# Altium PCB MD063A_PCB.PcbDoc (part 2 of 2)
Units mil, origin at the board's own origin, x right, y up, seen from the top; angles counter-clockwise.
Board outline 3360 x 2682 mil, 4 copper layers (Top Layer, Signal Layer 1, Signal Layer 2, Bottom Layer), stack 61.6 mil thick; 162 components, 89 nets, 431 pads, 221 vias.
Unrouted connection lines stored in the file: 2.
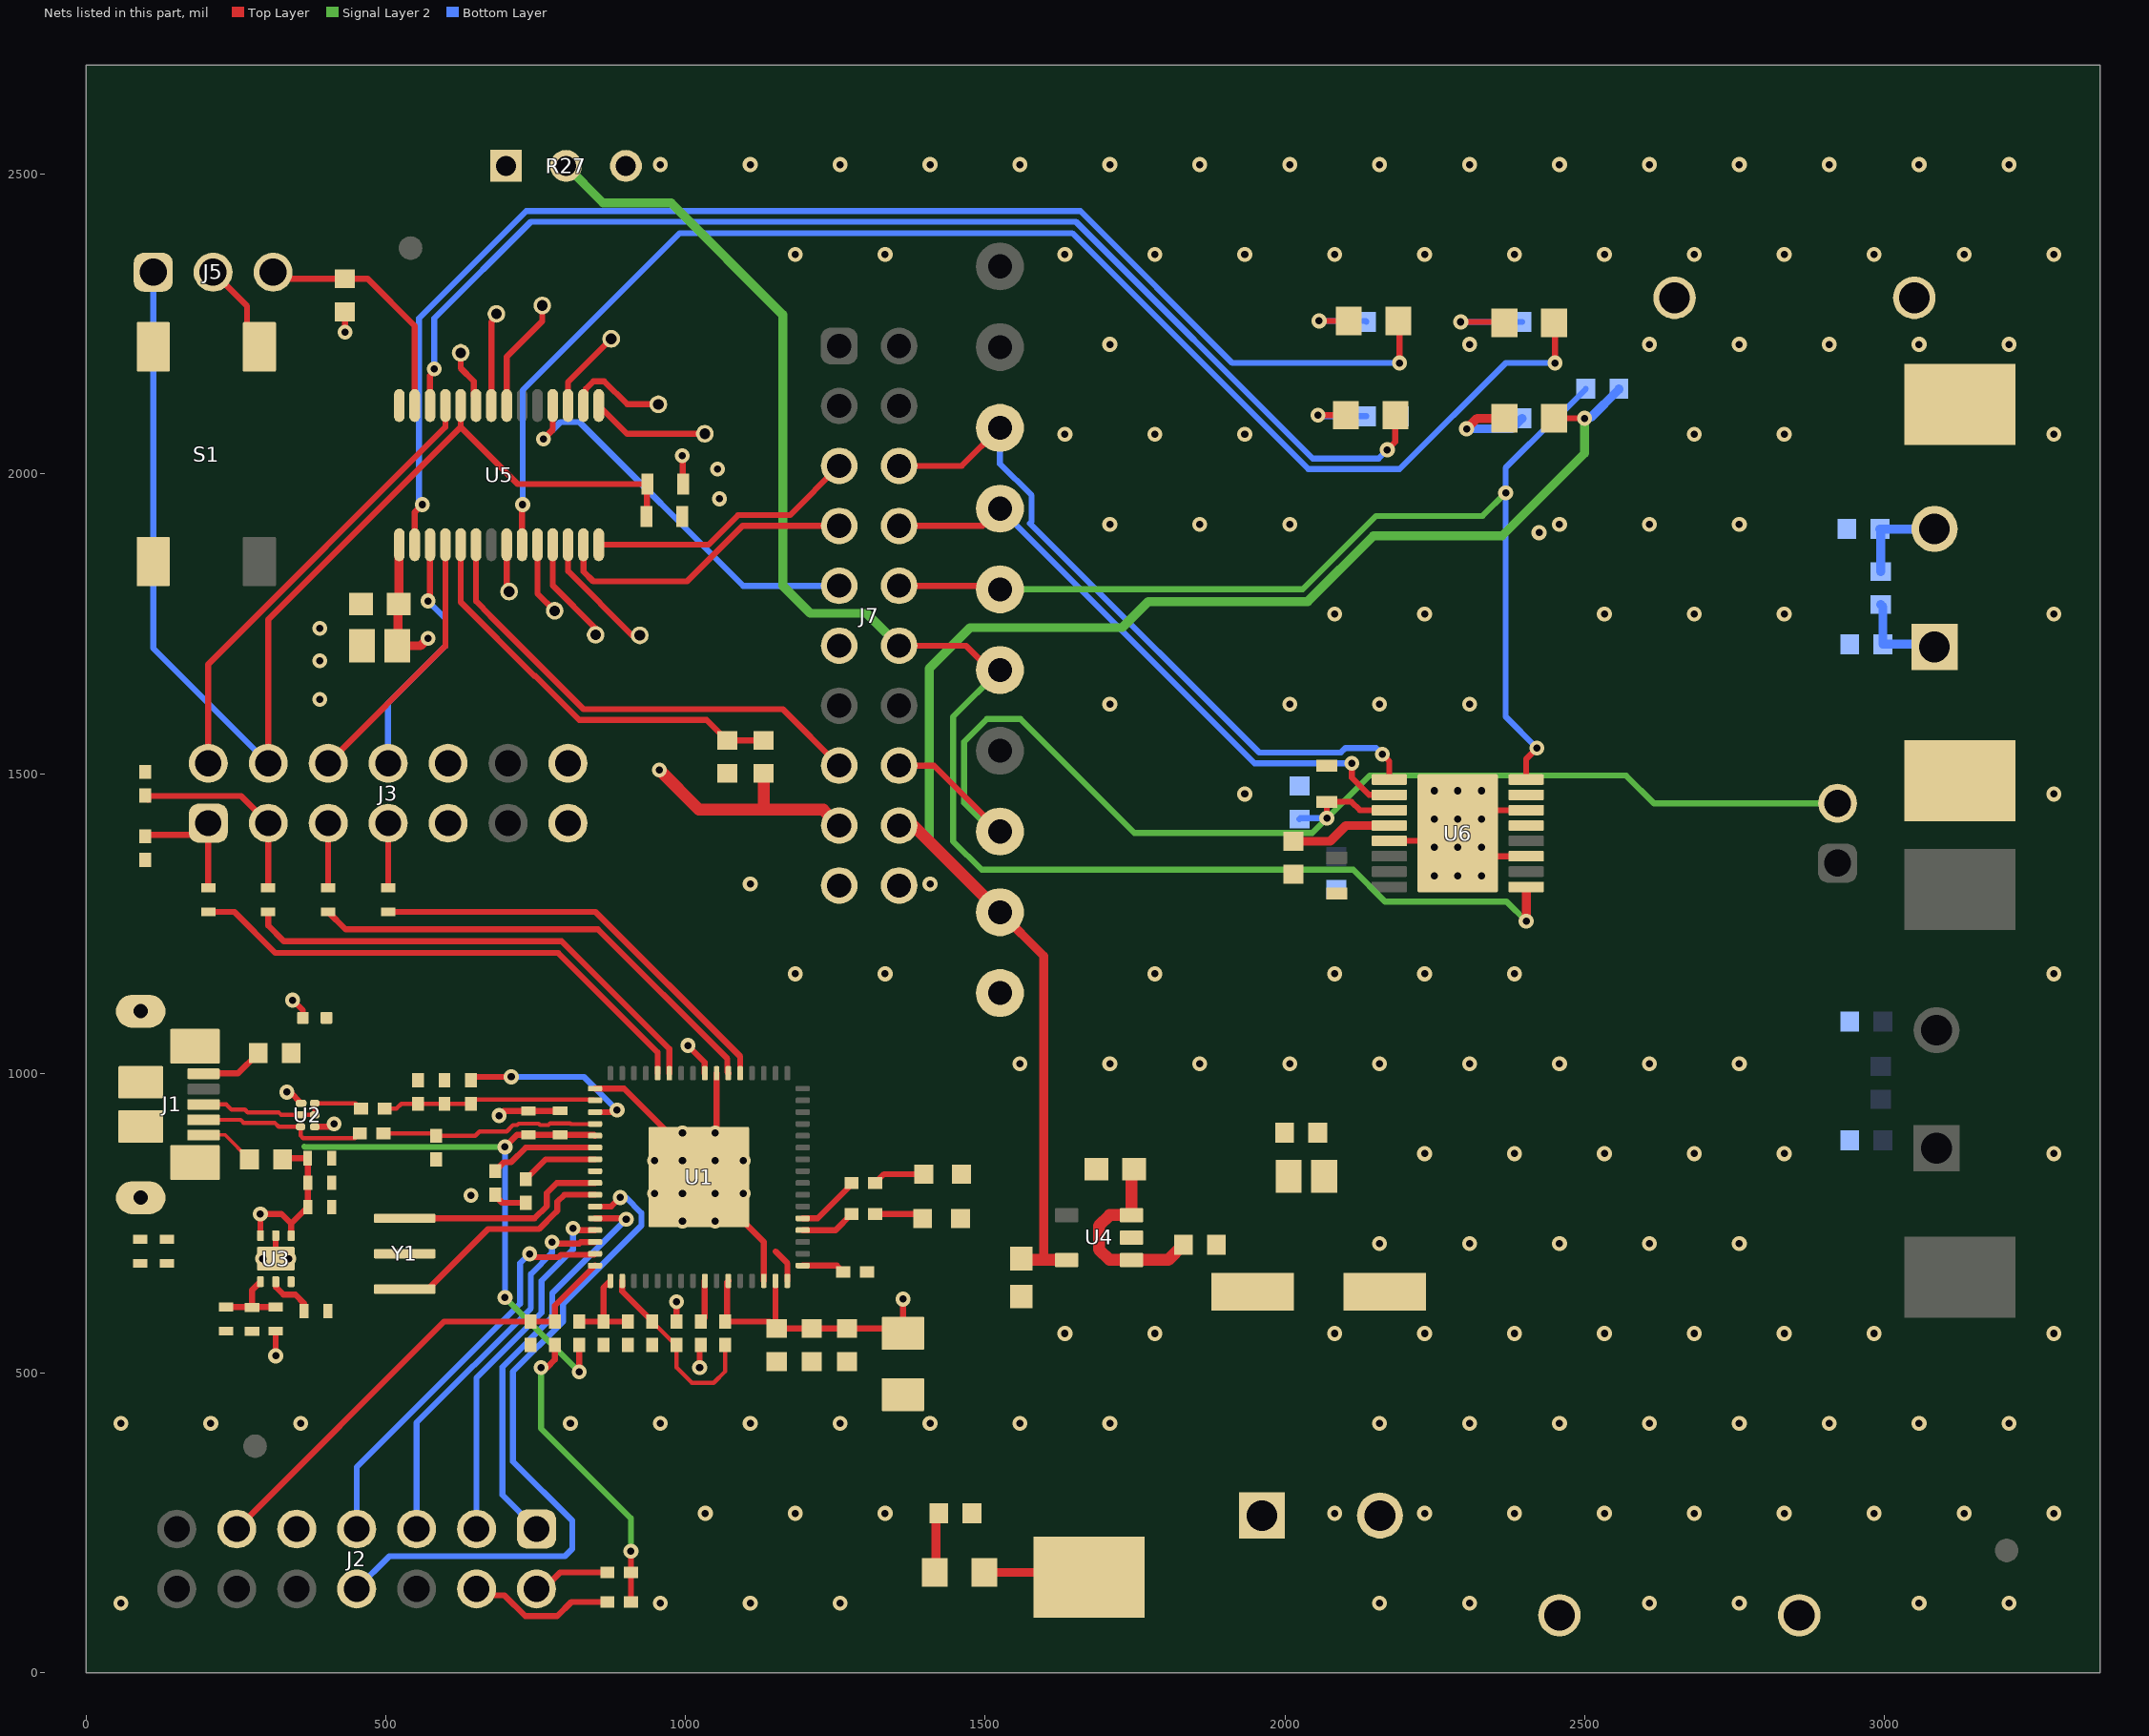
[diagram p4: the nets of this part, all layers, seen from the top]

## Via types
v1: diameter 25/25/25/25 (per signal layer), hole 12, Top Layer to Bottom Layer, 136 vias
v2: diameter 25/25/25/25 (per signal layer), hole 12, Top Layer to Bottom Layer, tented both sides, 85 vias

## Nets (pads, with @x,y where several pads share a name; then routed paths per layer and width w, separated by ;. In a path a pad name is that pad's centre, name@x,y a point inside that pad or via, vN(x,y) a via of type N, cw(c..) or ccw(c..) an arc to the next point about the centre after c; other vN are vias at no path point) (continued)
BIN1: J7.6 TP18.1 U6.9 | length 1177.7
  Top Layer w10: J7.6@1356.4,2013.34 1461.11,2013.34 TP18.1@1524.61,2076.84 ; v2(2162.56,1532.28) 2174.17,1520.67 U6.9@2174.17,1490.11
  Bottom Layer w10: TP18.1@1524.61,2076.84 1524.61,2016.92 1577.48,1964.05 1577.48,1920.25 1574.63,1917.4 1619.16,1872.88 1956.84,1535.2 2093.41,1535.2 2100.91,1542.7 2152.14,1542.7 v2(2162.56,1532.28)
BIN1_MCU: J7.5 U5.14 | length 455.5
  Top Layer w10: U5.14@855.32,1881.89 1038.52,1881.89 1087.85,1931.22 1174.27,1931.22 J7.5@1256.4,2013.34
BIN2: J7.8 TP19.1 U6.10 | length 1041.5
  Top Layer w10: J7.8@1356.4,1913.34 1495.8,1913.34 TP19.1@1524.61,1942.15 ; v2(2111.42,1517.32) 2111.42,1493.45 2140.34,1464.52 U6.10@2174.17,1464.52
  Bottom Layer w10: TP19.1@1524.61,1942.15 1949.43,1517.32 v2(2111.42,1517.32)
BIN2_MCU: J7.7 U5.13 | length 516.6
  Top Layer w10: U5.13@829.72,1881.89 829.72,1837.21 846.23,1820.71 1002.61,1820.71 1095.25,1913.34 J7.7@1256.4,1913.34
BIPROPI: C36.1 J6.2 J7.16 R25.2 TP23.1 U6.11 | length 2189.8
  Top Layer w10: J7.16@1356.4,1513.34 1414.65,1513.34 TP23.1@1524.61,1403.39 ; v2(2070,1425.48) R25.2@2070,1453.03 2110.95,1453.03 2125.05,1438.93 U6.11@2174.17,1438.93
  Signal Layer 2 w10: TP23.1@1524.61,1403.39 1512.36,1403.39 1464.57,1451.19 1464.57,1552.82 1502.71,1590.95 1558.97,1590.95 1748.84,1401.08 2045.6,1401.08 v2(2070,1425.48) 2141.31,1496.79 2569.36,1496.79 2615.6,1450.55 J6.2@2922,1450.55
  Bottom Layer w10: C36.1@2024.2,1424.17 2025.51,1425.48 v2(2070,1425.48)
BIPROPI_MCU: J7.15 U5.6 | length 814.1
  Top Layer w10: U5.6@650.59,1881.89 650.59,1787.53 674.9,1763.23 674.9,1762.61 830.03,1607.48 1162.26,1607.48 J7.15@1256.4,1513.34
BOUT1: C39.2 C40.1 J9.2 TP15.1 U6.7 | length 218.6
  Top Layer w15: TP15.1@3126,2060.12 TP15.1@3126,2116.14
  Bottom Layer w15: C39.2@2994,1837.12 2994,1906.68 C40.1@2992.68,1908 3083.49,1908 J9.2@3083.72,1908.23
BOUT2: C39.1 C42.1 J9.1 TP14.1 U6.5 | length 211.6
  Top Layer w15: TP14.1@3126,1488 TP14.1@3126,1544.03
  Bottom Layer w15: C39.1@2994,1782 2997.56,1778.44 C42.1@2997.56,1716 3079.1,1716 J9.1@3083.72,1711.38
DEV_ID: R21.1 R22.2 U5.5 | length 697.1
  Top Layer w10: U5.5@625,1881.89 625,1785.81 748.21,1662.6 749.63,1662.6 822.62,1589.61 1035.29,1589.61 R22.2@1069.44,1555.46 R21.1@1130.58,1555.46
EZFET_AVBUS: C18.1 R14.1 R15.2 U1.1 | length 153.6
  Top Layer w10: R14.1@822.83,586.01 C18.1@863.43,586.01 ; U1.1@874.68,653.73 863.43,642.48 C18.1@863.43,586.01 ; R15.2@904.03,586.01 C18.1@863.43,586.01
EZFET_AVCC2ADC: C19.1 R16.1 R17.2 U1.2 | length 326.4
  Top Layer w7: C19.1@944.63,586.01 984,546.64 R17.2@985.23,546.64 985.23,509.11 1010.7,483.65 1047.1,483.65 1066.44,502.98 R16.1@1066.44,546.64
  Top Layer w10: U1.2@894.36,653.73 894.36,636.28 C19.1@944.63,586.01
EZFET_D_N: C11.1 R4.2 U1.52 | length 365.8
  Top Layer w7: R4.2@496.06,900 580.01,900 C11.1@584.15,895.85 649.3,895.85 656.58,903.14 701.65,903.14 712.14,913.63 718.98,913.63 721.48,916.13 754.9,916.13 757.4,913.63 771.38,913.63 774.13,916.38 807.56,916.38 808.58,915.35 848.9,915.35 U1.52@849.09,915.54
EZFET_D_P: C12.1 R5.2 R6.2 R7.1 U1.50 | length 358.9
  Top Layer w7: R5.2@498.02,940.95 517.72,940.95 525.77,949 R6.2@553.64,949 C12.1@597.93,949 R7.1@642.22,949 648.13,954.91 648.13,956.38 847.61,956.38 U1.50@849.09,954.91
EZFET_LED0: R1.2 U1.20 | length 92.6
  Top Layer w10: U1.20@1195.54,738.37 1250.29,738.37 R1.2@1277.07,765.14
EZFET_LED1: R2.2 U1.21 | length 107.2
  Top Layer w10: U1.21@1195.54,758.06 1220.47,758.06 1277.07,814.65 R2.2@1277.07,816.93
EZFET_PUR: R7.2 U1.51 | length 307.1
  Top Layer w10: R7.2@642.22,988.37 647.95,994.09 v2(709.33,994.09) ; U1.51@849.09,935.22 882.14,935.22 v2(885.83,938.91)
  Bottom Layer w10: v2(709.33,994.09) 830.64,994.09 v2(885.83,938.91)
EZFET_RST: C24.1 J2.11 R19.1 U1.64 | length 795.3
  Top Layer w10: J2.11@251.38,239.76 597.62,586.01 C24.1@741.63,586.01 R19.1@782.23,586.01 782.23,612.46 U1.64@849.09,679.32
EZFET_TCK: J2.7 U1.63 | length 692.6
  Top Layer w10: v2(739.87,698.82) 745.56,693.13 788.07,693.13 792.13,697.19 847.27,697.19 U1.63@849.09,699
  Bottom Layer w10: J2.7@451.38,239.76 451.38,342.66 724.19,615.47 724.19,683.14 v2(739.87,698.82)
EZFET_TDI: J2.3 U1.61 | length 606.4
  Top Layer w10: v2(812.36,741.49) 815.48,738.37 U1.61@849.09,738.37
  Bottom Layer w10: J2.3@651.38,239.76 651.38,492.1 759.94,600.67 759.94,653.73 812.36,706.14 v2(812.36,741.49)
EZFET_TDO: J2.1 U1.60 | length 678.5
  Top Layer w10: U1.60@849.09,758.06 899.35,758.06 v2(901.08,756.33)
  Bottom Layer w10: J2.1@751.38,239.76 694.39,296.75 694.39,509.84 777.81,593.26 777.81,633.06 v2(901.08,756.33)
EZFET_TEST: J2.8 U1.59 | length 1171.8
  Top Layer w10: U1.59@849.09,777.74 876.17,777.74 v2(891.29,792.86)
  Bottom Layer w10: J2.8@451.38,139.76 506.02,194.41 799,194.41 811.15,206.56 811.15,253.64 712.26,352.53 712.26,502.43 795.69,585.86 795.69,615.05 926.46,745.82 926.46,766.84 900.43,792.86 v2(891.29,792.86)
EZFET_TMS: J2.5 U1.62 | length 646
  Top Layer w10: v2(777.56,718.5) 779.94,716.12 822.87,716.12 825.25,718.5 848.9,718.5 U1.62@849.09,718.69
  Bottom Layer w10: J2.5@551.38,239.76 551.38,417.38 742.07,608.07 742.07,665.13 777.56,700.62 v2(777.56,718.5)
EZFET_UARTRXD: R10.1 U1.38 | length 792.3
  Top Layer w10: R10.1@403.86,1269.37 433.08,1240.16 854,1240.16 1069.72,1024.44 1069.72,1001.99 U1.38@1071.53,1000.18
EZFET_UARTTXD: R11.1 U1.37 | length 715.1
  Top Layer w10: R11.1@504.05,1269.37 850.06,1269.37 1091.21,1028.22 U1.37@1091.21,1000.18
EZFET_USB_Shield: C5.1 J1.6 J1.7 J1.8 J1.9 J1.10 J1.11 R3.2
EZFET_V18: C2.1 U1.55 | length 129
  Top Layer w10: C2.1@733.76,823.36 766.88,856.48 U1.55@849.09,856.48
EZFET_VBUS: C9.2 C13.1 C14.1 C15.1 C23.1 C25.1 L1.2 R14.2 U1.53 U2.1 U3.4 U3.6 | length 1311.4
  Top Layer w10: U3.6@290.85,729.15 290.85,764.99 v2(290.69,765.14) 325.96,765.14 342.03,749.08 ; L1.2@327.87,856.48 329.79,858.4 C13.1@369.59,858.4 369.9,858.09 C14.1@369.9,817.46 C15.1@369.9,776.96 342.03,749.08 ; v2(334.76,968.69) 340.25,968.69 U2.1@358.76,950.18 ; U3.4@342.03,729.15 342.03,749.08 ; v2(344.49,1122.05) 361.71,1104.82 C9.2@361.71,1092.52 ; v2(698.82,877.15) 718.92,897.26 C25.1@738.19,897.26 790.6,897.26 C23.1@790.85,897.51 847.43,897.51 U1.53@849.09,895.85 ; v2(822.83,501.97) R14.2@822.83,546.64
  Signal Layer 2 w10: 364.17,877.97 364.99,877.15 v2(698.82,877.15) ; v2(698.82,625.98) v2(822.83,501.97)
  Bottom Layer w10: v2(698.82,625.98) v2(698.82,877.15)
EZFET_VCC: C6.1 C7.1 C8.1 C10.1 J3.9 R12.1 R13.1 R16.2 R18.2 R19.2 U1.11 U1.15 U1.40 | length 1114.6
  Top Layer w10: v2(316.44,528.71) R18.2@316.44,569.95 ; v2(758.86,509.11) 769.02,509.11 782.23,522.33 R19.2@782.23,546.64 ; R12.1@908.96,118.11 R13.1@908.96,167.32 v2(908.96,202.69) ; v2(1003.94,1046.44) 1032.16,1018.22 U1.40@1032.16,1000.18 ; U1.11@1071.53,653.73 1069.44,651.64 1069.44,589.01 R16.2@1066.44,586.01 1140.29,586.01 C7.1@1150.27,576.04 ; U1.15@1150.27,653.73 C7.1@1150.27,576.04 ; v2(1362.73,623.41) C6.1@1362.73,566.33 1354.86,574.2 C10.1@1269.19,574.2 C8.1@1210.65,574.2 C7.1@1152.1,574.2 C7.1@1150.27,576.04
  Signal Layer 2 w10: v2(758.86,509.11) 758.86,407.55 908.96,257.46 v2(908.96,202.69)
EZFET_VCORE: C3.1 U1.17 | length 72.1
  Top Layer w10: U1.17@1195.54,679.32 1252.66,679.32 C3.1@1263.29,668.69
EZFET_VREF: C1.1 U1.9 | length 70.3
  Top Layer w10: C1.1@1025.83,586.01 1032.16,592.33 U1.9@1032.16,653.73
EZFET_VUSB: C4.1 U1.54 | length 182.7
  Top Layer w10: C4.1@682.58,836.99 697.36,851.78 709.33,851.78 733.72,876.17 U1.54@849.09,876.17
EZFET_XT2IN: U1.57 Y1.1 | length 355
  Top Layer w10: Y1.1@531.5,758.06 748.21,758.06 768.45,778.3 768.45,800.38 785.19,817.11 U1.57@849.09,817.11
EZFET_XT2OUT: U1.58 Y1.3 | length 389.5
  Top Layer w10: Y1.3@531.5,639.95 570.53,639.95 670.77,740.18 755.62,740.18 783.68,768.25 ; 785.19,769.75 786.33,770.89 786.33,785.97 797.78,797.43 U1.58@849.09,797.43
GND: C1.2 C2.2 C3.2 C4.2 C5.2 C6.2 C7.2 C8.2 C9.1 C10.2 C11.2 C12.2 C13.2 C14.2 C15.2 C16.1 C17.1 C18.2 C19.2 C20.2 C21.2 C22.2 C23.2 C24.2 C25.2 C26.2 C27.2 C28.2 C29.2 C30.2 C31.2 C32.2 C33.2 C34.2 C35.2 C36.2 C38.2 C40.2 C41.2 C42.2 D1.1 D2.1 J2.9 J3.13 J3.14 J4.2 J7.19 J7.20 L2.2 R3.1 R6.1 R15.1 R17.1 R22.1 R24.1 R25.1 R27.3 R28.1 R29.1 R30.1 R31.1 S1.3 S1.4 TP6.1 TP6.2 TP7.1 TP7.2 TP25.1 U1.14 U1.16 U1.39 U1.49 U1.56 U1.65 U2.4 U3.3 U3.5 U3.7@316.44,690.76 U4.2 U5.28 U6.3 U6.6 U6.13 U6.17 Y1.2 | length 1385.4
  Top Layer w10: U3.7@316.44,690.76 U3.5@316.44,729.15 ; U2.4@381.4,910.81 409.01,910.81 v2(413.73,915.54) ; C4.2@682.58,797.62 682.58,795.66 694.24,783.99 C2.2@733.76,783.99 ; v2(688.98,929.51) 696.72,937.26 C25.2@738.19,937.26 790.6,937.26 C23.2@790.85,937.51 ; U1.49@849.09,974.59 897.4,974.59 1022.31,849.68 U1.65@1022.31,826.96 ; R17.1@985.23,586.01 v2(985.23,618.8) ; v2(1023.62,509.11) 1023.62,544.43 C1.2@1025.83,546.64 ; U1.39@1051.84,1000.18 1051.84,856.48 v2(1049.68,854.32) U1.65@1022.31,826.96 ; U1.14@1130.58,653.73 1130.58,718.69 v2(1049.68,799.59) U1.65@1022.31,826.96 ; 1150.27,702.78 1169.95,683.1 U1.16@1169.95,653.73 ; U6.13@2174.17,1387.75 2275.55,1387.75 U6.17@2288.34,1400.55 ; U6.17@2319.84,1369.05 U6.17@2288.34,1400.55 ; U6.17@2326.73,1362.16 U6.3@2402.51,1362.16 ; U6.6@2402.51,1438.93 2326.73,1438.93 U6.17@2288.34,1400.55
  other v1: 58,116 958,116 1108,116 1258,116 2158,116 2308,116 2608,116 2758,116 3058,116 3208,116 1033,266 1183,266 1333,266 2083,266 2233,266 2383,266 2533,266 2683,266 2833,266 2983,266 3133,266 3283,266 58,416 208,416 358,416 808,416 958,416 1108,416 1258,416 1408,416 1558,416 1708,416 2158,416 2308,416 2458,416 2608,416 2758,416 2908,416 3058,416 3208,416 1633,566 1783,566 2083,566 2233,566 2383,566 2533,566 2683,566 2833,566 2983,566 3283,566 2158,716 2308,716 2458,716 2608,716 2758,716 2233,866 2383,866 2533,866 2683,866 2833,866 3283,866 1558,1016 1708,1016 1858,1016 2008,1016 2158,1016 2308,1016 2458,1016 2608,1016 2758,1016 1183,1166 1333,1166 1783,1166 2083,1166 2233,1166 2383,1166 3283,1166 1108,1316 1408,1316 1933,1466 3283,1466 1708,1616 2008,1616 2158,1616 2308,1616 2083,1766 2233,1766 2533,1766 2683,1766 2833,1766 3283,1766 1708,1916 1858,1916 2008,1916 2458,1916 2608,1916 2758,1916 1633,2066 1783,2066 1933,2066 2683,2066 2833,2066 3283,2066 1708,2216 2608,2216 2758,2216 2908,2216 3058,2216 3208,2216 1183,2366 1333,2366 1633,2366 1783,2366 1933,2366 2083,2366 2233,2366 2383,2366 2533,2366 2683,2366 2833,2366 2983,2366 3133,2366 3283,2366 958,2516 1108,2516 1258,2516 1408,2516 1558,2516 1708,2516 1858,2516 2008,2516 2158,2516 2308,2516 2608,2516 3058,2516 3208,2516
  other v2: 294.78,690.76 338.09,690.76 994.95,753.14 1049.68,753.14 642.22,796.41 948.49,799.59 994.95,799.59 1096.13,799.59 948.49,854.32 994.95,854.32 1096.13,854.32 994.95,900.77 1049.68,900.77 2248.97,1329.68 2288.34,1329.68 2327.71,1329.68 2248.97,1376.93 2288.34,1376.93 2327.71,1376.93 2248.97,1424.17 2288.34,1424.17 2327.71,1424.17 2248.97,1471.41 2288.34,1471.41 2327.71,1471.41 389.71,1624.02 389.71,1688.45 389.71,1742.46 2424,1902 1056.54,1958.44 1053.38,2007.87 2308,2216 2458,2516 2758,2516 2908,2516
GUI_STATUS: D4.2 U5.9 | length 2393.4
  Top Layer w10: U5.9@727.36,1881.89 727.36,1947.83 v2(728.35,1948.82) ; D4.2@2448.82,2252.02 2450.79,2250.05 v2(2450.79,2185.04)
  Bottom Layer w10: v2(728.35,1948.82) 728.35,2139.61 990.43,2401.69 1645.1,2401.69 2038.92,2007.87 2191.1,2007.87 2368.26,2185.04 v2(2450.79,2185.04)
MCU_STATUS: D3.2 U5.2 | length 2271.2
  Top Layer w10: U5.2@548.23,1881.89 548.23,1936.02 v2(561.02,1948.82) ; D3.2@2189.13,2255.17 2191.1,2253.2 v2(2191.1,2185.04)
  Bottom Layer w10: v2(561.02,1948.82) 555.33,1954.51 555.33,2259.64 734.22,2438.52 1658.82,2438.52 1912.31,2185.04 v2(2191.1,2185.04)
MCU_UARTRXD: J3.8 U5.3 | length 417.6
  Top Layer w10: v2(570.37,1787.95) 573.82,1791.39 U5.3@573.82,1881.89
  Bottom Layer w10: J3.8@503.86,1517.32 503.86,1617.32 599.41,1712.87 599.41,1758.91 v2(570.37,1787.95)
MCU_UARTTXD: J3.6 U5.4 | length 445.6
  Top Layer w10: J3.6@403.86,1517.32 599.41,1712.87 U5.4@599.41,1881.89
NetC16_2: C16.2 J3.1 R8.2 | length 216.6
  Top Layer w10: C16.2@103.34,1397.64 184.18,1397.64 J3.1@203.86,1417.32 R8.2@203.86,1309.37
NetC17_2: C17.2 J3.3 R9.2 | length 333.2
  Top Layer w10: C17.2@103.34,1456.69 103.34,1462.68 258.51,1462.68 J3.3@303.86,1417.32 R9.2@303.86,1309.37
NetC20_1: C20.1 U3.2 | length 80.2
  Top Layer w10: U3.2@316.44,652.38 316.44,643.36 329.16,630.64 349.11,630.64 363.68,616.08 C20.1@363.68,603.41
NetC21_1: C21.1 C22.1 R18.1 U3.1 | length 131.2
  Top Layer w10: C22.1@233.76,609.95 C21.1@276.91,609.95 ; C21.1@276.91,609.63 C21.1@276.91,609.95 ; U3.1@290.85,652.38 276.91,638.44 C21.1@276.91,609.95 ; R18.1@316.44,609.95 C21.1@276.91,609.95
NetC26_1: C26.1 R20.1 U4.1 U4.3 | length 337.8
  Top Layer w15: C26.1@1743.98,837.35 C26.1@1746.98,840.36
  Top Layer w20: C26.1@1743.98,837.35 U4.3@1743.98,763.4 1707.56,763.4 1689.84,745.68 1689.84,706.31 1707.56,688.6 U4.1@1743.98,688.6 1805.31,688.6 R20.1@1830.71,714
NetD1_2: D1.2 R1.1 | length 82.2
  Top Layer w10: R1.1@1316.44,765.14 1388.4,765.14 D1.2@1395.67,757.87
NetD2_2: D2.2 R2.1 | length 87.4
  Top Layer w10: R2.1@1316.44,816.93 1331.38,831.88 D2.2@1397.64,831.88
NetD3_1: D3.1 R28.2 | length 128.9
  Top Layer w10: v2(2057.09,2255.17) D3.1@2106.45,2255.17
  Bottom Layer w10: v2(2057.09,2255.17) 2134.55,2255.17 R28.2@2135.98,2253.74
NetD4_1: D4.1 R29.2 | length 175.8
  Top Layer w10: v2(2293.31,2253.54) 2364.61,2253.54 D4.1@2366.14,2252.02
  Bottom Layer w10: v2(2293.31,2253.54) R29.2@2395.67,2253.54
NetD5_1: D5.1 R30.2 | length 128
  Top Layer w10: v2(2055.07,2097.79) D5.1@2101.53,2097.79
  Bottom Layer w10: v2(2055.07,2097.79) 2056.5,2096.37 R30.2@2135.98,2096.37
NetD6_1: D6.1 R31.2 | length 92.6
  Top Layer w15: D6.1@1417.81,175.38 1417.81,261.01 R31.2@1422.73,265.93
NetD7_1: D7.1 R33.2 | length 169.9
  Top Layer w15: v2(2303.15,2075.26) 2320.56,2092.67 D7.1@2366.14,2092.67
  Bottom Layer w15: v2(2303.15,2075.26) 2378.26,2075.26 R33.2@2395.67,2092.67
NetJ1_1: J1.1 L1.1 | length 94.2
  Top Layer w6: J1.1@195.86,896.9 196.5,897.54 231.69,897.54 L1.1@272.75,856.48
NetJ1_5: J1.5 L2.1 | length 105.5
  Top Layer w10: J1.5@195.86,999.26 196.5,999.9 253.36,999.9 L2.1@287.11,1033.65
NetJ2_2: J2.2 R13.2 | length 129.6
  Top Layer w10: J2.2@751.38,139.76 763.4,139.76 790.96,167.32 R13.2@869.59,167.32
NetJ2_4: J2.4 R12.2 | length 246.8
  Top Layer w10: J2.4@651.38,139.76 661.89,129.25 697.75,129.25 732.59,94.41 785.83,94.41 809.53,118.11 R12.2@869.59,118.11
NetJ3_5: J3.5 R10.2 | length 108
  Top Layer w10: R10.2@403.86,1309.37 J3.5@403.86,1417.32
NetJ3_7: J3.7 R11.2 | length 108
  Top Layer w10: J3.7@503.86,1417.32 504.05,1417.14 R11.2@504.05,1309.37
NetJ5_2: J5.2 S1.1 | length 156.4
  Top Layer w10: J5.2@212,2336.43 268.54,2279.89 268.54,2232.64 S1.1@289.17,2212.01
NetTP2_1: TP2.1 U5.23 | length 98.4
  Top Layer w10: TP2.1@625,2201.94 625,2176.34 646.73,2154.61 646.73,2129.6 650.59,2125.74 U5.23@650.59,2114.17
NetTP3_1: TP3.1 U5.8 | length 79.8
  Top Layer w10: U5.8@701.77,1881.89 701.77,1807.63 TP3.1@705.71,1803.7
NetTP4_1: TP4.1 U5.15 | length 196.4
  Top Layer w10: U5.15@855.32,2114.17 902.56,2066.93 TP4.1@1032.16,2066.93
NetTP5_1: TP5.1 U5.21 | length 191.3
  Top Layer w10: U5.21@701.77,2114.17 701.77,2195.51 761.1,2254.84 TP5.1@761.1,2280.91
NetTP8_1: TP8.1 U5.16 | length 172.8
  Top Layer w10: U5.16@829.72,2114.17 831.69,2116.14 833.58,2116.14 833.58,2141.88 846.31,2154.61 864.32,2154.61 902.78,2116.14 TP8.1@954.72,2116.14
NetTP9_1: TP9.1 U5.12 | length 208.2
  Top Layer w10: U5.12@804.13,1881.89 804.13,1837.52 911.02,1730.64 TP9.1@923.65,1730.64
NetTP10_1: TP10.1 U5.11 | length 180
  Top Layer w10: U5.11@778.54,1881.89 778.54,1813.98 850.06,1742.46 TP10.1@850.06,1731.55
NetTP11_1: TP11.1 U5.10 | length 122.2
  Top Layer w10: U5.10@752.95,1881.89 752.95,1800.48 TP11.1@781.78,1771.65
NetTP26_1: TP26.1 U5.22 | length 156.3
  Top Layer w10: U5.22@676.18,2114.17 676.18,2253.42 684.48,2261.72 TP26.1@684.48,2267
NetTP27_1: TP27.1 U5.17 | length 141
  Top Layer w10: U5.17@804.13,2114.17 804.13,2153.46 TP27.1@876.06,2225.38
nFAULT: J7.10 R32.1 R33.1 TP20.1 U6.8 | length 1818.4
  Top Layer w10: J7.10@1356.4,1813.34 1518.72,1813.34 TP20.1@1524.61,1807.46 ; U6.8@2402.51,1490.11 2402.51,1524.78 v2(2420.43,1542.7)
  Signal Layer 2 w10: TP20.1@1524.61,1807.46 2029.73,1807.46 2152.14,1929.87 2329.63,1929.87 v2(2368.26,1968.5)
  Bottom Layer w10: v2(2420.43,1542.7) 2368.26,1594.86 2368.26,2010.15 R33.1@2450.79,2092.67 2452.67,2092.67 R32.1@2502,2142
nFAULT_MCU: J7.9 U5.18 | length 681
  Top Layer w10: v2(762.87,2058.04) 778.54,2073.72 U5.18@778.54,2114.17
  Bottom Layer w10: v2(762.87,2058.04) 791.24,2086.42 823.03,2086.42 1096.11,1813.34 J7.9@1256.4,1813.34
PUSH: J5.3 R26.1 U5.27 | length 406.1
  Top Layer w10: J5.3@312,2336.43 322.96,2325.47 R26.1@432,2325.47 469.79,2325.47 548.23,2247.03 U5.27@548.23,2114.17
RST/SBWTDIO: C35.1 J3.4 J5.1 R23.1 U5.24 | length 2033.9
  Top Layer w10: J3.4@303.86,1517.32 303.86,1757.01 625,2078.14 ; U5.24@625,2114.17 625,2078.14 ; C35.1@934.67,1929.21 935.56,1930.1 935.56,1982.14 R23.1@936.45,1983.03 720.11,1983.03 625,2078.14
  Bottom Layer w10: J5.1@112,2336.43 112,1709.19 J3.4@303.86,1517.32
STALL: D5.2 U5.26 | length 2037.7
  Top Layer w10: U5.26@573.82,2114.17 573.82,2164.25 580.71,2171.14 v2(580.71,2175.2) ; v2(2170.87,2040.16) 2184.21,2053.5 D5.2@2184.21,2097.79
  Bottom Layer w10: v2(580.71,2175.2) 580.71,2259.39 741.97,2420.65 1651.42,2420.65 2046.32,2025.75 2156.46,2025.75 v2(2170.87,2040.16)
T_RST_RST: R9.1 U1.43 | length 818
  Top Layer w10: R9.1@303.86,1269.37 303.86,1246.4 329.79,1220.47 793.47,1220.47 973.1,1040.85 U1.43@973.1,1000.18
T_TEST_TCKC: R8.1 U1.44 | length 881.6
  Top Layer w10: R8.1@203.86,1269.37 247.48,1269.37 316.06,1200.79 787.88,1200.79 953.42,1035.25 U1.44@953.42,1000.18
TST/SBWTCK: J3.2 U5.25 | length 760.7
  Top Layer w10: J3.2@203.86,1517.32 203.86,1682.28 599.41,2077.83 U5.25@599.41,2114.17
USB_D_N: J1.2 R4.1 U2.3 | length 285.7
  Top Layer w7: J1.2@195.86,922.49 257.84,922.49 262.82,917.51 314.66,917.51 321.36,910.81 U2.3@357.77,910.81 357.77,896.17 362.03,891.92 362.14,892.03 384,892.03 384.37,891.66 423.62,891.66 423.99,892.03 448.73,892.03 R4.1@456.69,900
USB_D_P: J1.3 R5.1 U2.2 U2.5 U2.6 | length 293.6
  Top Layer w7: J1.3@195.86,948.08 233.79,948.08 235.9,945.97 242.38,939.49 264.88,939.49 269.87,934.51 321.71,934.51 325.71,930.5 U2.2@357.77,930.5 U2.5@381.4,930.5 U2.6@381.4,950.18 449.42,950.18 R5.1@458.65,940.95
VCC: C27.1 C29.1 C32.1 D7.2 J3.10 J7.17 J7.18 R21.2 R23.2 R26.2 R27.1 R32.2 TP24.1 U4.5 U5.1 | length 3507
  Top Layer w10: v2(432,2236.29) R26.2@432,2270.35 ; v2(994.67,2030.31) 995.56,2029.42 995.56,1983.92 R23.2@996.45,1983.03 ; D7.2@2448.82,2092.67 v2(2500,2092.67)
  Top Layer w15: U5.1@522.64,1881.89 522.15,1881.4 522.15,1783.52 C29.1@521.65,1783.03 520.42,1781.8 520.42,1714.57 C27.1@519.19,1713.34 558.07,1713.34 v2(570.37,1725.64) ; TP24.1@1524.61,1268.7 1597.51,1195.79 1597.51,689.25
  Top Layer w20: v2(956.45,1506.01) 1022.74,1439.72 1131.89,1439.72 ; R21.2@1130.58,1500.34 1130.58,1441.03 1131.89,1439.72 ; J7.17@1256.4,1413.34 1230.02,1439.72 1131.89,1439.72 ; J7.18@1356.4,1413.34 1379.97,1413.34 TP24.1@1524.61,1268.7 ; C32.1@1559.97,689.25 1597.51,689.25 1635.05,689.25 U4.5@1635.71,688.6
  Signal Layer 2 w15: TP24.1@1524.61,1268.7 1406.4,1386.91 1406.4,1675.24 1474.67,1743.52 1728.52,1743.52 1772.09,1787.09 2038.17,1787.09 2147.72,1896.63 2362.2,1896.63 2500,2034.43 v2(2500,2092.67)
  Bottom Layer w15: v2(2500,2092.67) 2501.91,2094.59 2510.69,2094.59 2557.12,2141.02 R32.2@2557.12,2142
VM: C28.1 C30.1 C31.1 C33.1 D6.2 J4.1 R20.2 TP1.1 U6.12 | length 348.7
  Top Layer w15: D6.2@1498.49,167.32 1665.1,167.32 TP1.1@1673.23,159.19 ; C33.1@2014.46,1387.12 2075.48,1387.12 2101.71,1413.34 U6.12@2174.17,1413.34
VREF: J7.12 R27.2 TP21.1 U6.1 | length 2723.8
  Top Layer w10: J7.12@1356.4,1713.34 1467.87,1713.34 1508.44,1672.77 TP21.1@1524.61,1672.77
  Top Layer w15: v2(2402.51,1253.71) U6.1@2402.51,1310.98
  Signal Layer 2 w10: TP21.1@1524.61,1672.77 1446.69,1594.86 1446.69,1386.93 1494.09,1339.52 2113.84,1339.52 2166.93,1286.43 2369.79,1286.43 v2(2402.51,1253.71)
  Signal Layer 2 w15: R27.2@800.61,2514 862.62,2451.99 975.95,2451.99 1162.26,2265.69 1162.26,1813.34 1208.14,1767.46 1302.28,1767.46 J7.12@1356.4,1713.34
VREF_MCU: J7.11
pads on no net: FID1.1 FID2.1 FID3.1 H1.0 H2.0 H3.0 H4.0 J1.4 J2.6 J2.10 J2.12 J2.13 J2.14 J3.11 J3.12 LBL1.0 S1.2 SH-J1.0 SH-J2.0 SH-J3.0 SH-J4.0 SH-J5.0 SH-J6.0 SH-J7.0 SH-J10.0 SH-J11.0 SH-J12.0 SH-J13.0 SH-J14.0 SH-J15.0 SH-J16.0 SH-J17.0 SH-J18.0 SH-J19.0 SH-J20.0 U1.3 U1.4 U1.5 U1.6 U1.7 U1.8 U1.10 U1.12 U1.13 U1.18 U1.19 U1.22 U1.23 U1.24 U1.25 U1.26 U1.27 U1.28 U1.29 U1.30 U1.31 U1.32 U1.33 U1.34 U1.35 U1.36 U1.41 U1.42 U1.45 U1.46 U1.47 U1.48 U3.7@298.72,690.76 U3.7@334.15,690.76 U4.4

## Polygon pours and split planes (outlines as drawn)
VM on Top Layer "Top Layer-VM" (solid, pour order 116): 1555.12,0 2015.44,0 2015.44,921.49 1979.75,968.15 1979.75,1369.05 2035.12,1369.05 2035.12,1406.8 1908,1406.8 1908,797.24 1868.08,797.24 1868.08,246.06 1556.29,246.06 1555.12,247.23
GND on Top Layer "TOP_LAYER_GND_P121" (solid, remove dead copper, pour order 121): 0,0 3360,0 3360,2682 0,2682
BOUT2 on Top Layer "TOP_LAYER_BOUT2_P114" (solid, remove dead copper, pour order 114): 2459.6,1446 2459.6,1408.68 2832,1408.68 2832,1532.28 3225,1532.28 3225,1812.41 3045,1812.41 3045,1608.24 2626.37,1608.24 2626.37,1446
AIPROPI on Top Layer "TOP_LAYER_AIPROPI_P112" (solid, remove dead copper, pour order 112): 2850,1392 2850,1284 3018,1284 3018,1392
BIPROPI on Top Layer "TOP_LAYER_BIPROPI_P104" (solid, remove dead copper, pour order 104): 2850,1410 2850,1524 3018,1524 3018,1410
AOUT2 on Top Layer "TOP_LAYER_AOUT2_P100" (solid, remove dead copper, pour order 100): 2459.6,1350.55 2459.6,1392.41 2538,1392.41 2832,1392.41 2832,1269.93 3225,1269.93 3225,989.8 3045,989.8 3045,1193.97 2628,1193.97 2628,1350.55
BOUT1 on Top Layer "TOP_LAYER_BOUT1_P098" (solid, remove dead copper, pour order 98): 2612.71,1632 2612.71,1481.09 2448.82,1481.09 2448.82,1711.38 2880,1711.38 2880,2083.46 3186,2083.68 3186,1842.21 3018,1842.21 3018,1632
AOUT1 on Top Layer "TOP_LAYER_AOUT1_P088" (solid, remove dead copper, pour order 88): 2628,1193.97 2628,1344 2448.82,1344 2448.82,1116 2880,1116 2880,708.21 3186,707.99 3186,960 3018,960 3018,1193.97
EZFET_USB_Shield on Top Layer "TOP_LAYER_EZFET_USB_SHIELD_P000" (solid, remove dead copper, pour order 0): 234.23,713.78 -1.77,713.78 -1.77,1165.19 234.23,1165.19
GND on Signal Layer 2 "SIGNAL_LAYER_2_GND_P118" (solid, remove dead copper, pour order 118): 0,0 3360,0 3360,2682 0,2682
VCC on Signal Layer 2 "SIGNAL_LAYER_2_VCC_P008" (solid, remove dead copper, pour order 8): 0,1476.38 1023.62,1476.38 1022.31,1477.69 1022.31,2555.63 0,2555.63
EZFET_VCC on Signal Layer 2 "SIGNAL_LAYER_2_EZFET_VCC_P006" (solid, remove dead copper, pour order 6): 0,492.13 1458.66,492.13 1458.66,1048.41 1456.69,1046.44 1023.62,1046.44 1023.62,1466.54 0,1466.54
EZFET_VBUS on Signal Layer 2 "SIGNAL_LAYER_2_EZFET_VBUS_P004" (solid, remove dead copper, pour order 4): -1.77,713.78 383.86,713.78 383.86,1165.19 -1.77,1165.19
GND on Bottom Layer "BOTTOM_LAYER_GND_P119" (solid, remove dead copper, pour order 119): 0,0 3360,0 3360,2682 0,2682
EZFET_USB_Shield on Bottom Layer "BOTTOM_LAYER_EZFET_USB_SHIELD_P010" (solid, remove dead copper, pour order 10): 234.23,713.6 -1.77,713.6 -1.77,1165.01 234.23,1165.01
GND on Signal Layer 1 "SIGNAL_LAYER_1_GND_P117" (solid, remove dead copper, pour order 117): 0,0 3360,0 3360,2682 0,2682

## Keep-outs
Keep-Out Layer:
  text ".Layer_Name" at 577,-858.49 h60

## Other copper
Top Layer:
  region net GND: 721.95,796.52 721.95,783.99 733.76,783.99 733.76,796.52
  region net BOUT1: 2373.03,1471.41 2439.14,1471.41 2448.82,1481.09 2612.71,1481.09 2612.71,1457.09 2373.03,1457.09
  region net AOUT2: 2521.07,1380 2527.07,1374 2527.07,1392.41 2373.03,1392.41 2373.03,1380
  region net GND: 837.43,840.63 944.37,840.63 944.37,832.55 837.43,832.27
  region net BOUT2: 2521.61,1421.09 2526,1425.48 2526,1421.09 2526,1408.68 2373.03,1408.68 2373.03,1421.09
  region net AOUT1: 2373.03,1329.68 2439.14,1329.68 2448.82,1320 2490,1320 2490,1332 2478,1344 2373.03,1344
  text ".Layer_Name" at 577,-858.49 h60
Bottom Layer:
  text ".Layer_Name" at 577,-858.49 h60

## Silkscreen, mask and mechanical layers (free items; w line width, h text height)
Top Overlay:
  lines w6: 436.96,753.14 350.12,753.14 350.12,882.05 436.96,882.05 436.96,742.36 451.38,727.94 451.38,630.64 491.63,590.39 492,519.08 ; 397.46,334.65 397.46,519.08 531.5,519.08 531.5,334.65 397.46,334.65
  lines w10: 80.22,239.76 80.22,314.96 151.38,314.96 ; 112.59,2401.69 112.59,2425.54 ; 316.26,2395.75 316.26,2419.76 ; 758.86,1715.63 758.86,1743.85 766.88,1751.87 ; 868.62,1716.54 884.52,1700.64 884.52,1700.62 ; 1979.75,1201.99 2478,1201.99 2478,1655.51 1979.75,1655.51 1979.75,1201.99 ; 2019.84,1978.54 2549.21,1978.54 2549.21,2332.48 2019.84,2332.48 2019.84,1978.54
  text ":)" at 3247.2,2584.89 h20
  text "RST" at 64.25,2438.52 h40
  text "PUSH" at 245.34,2438.52 h40
  text "VREF" at 738,2370 h40
  text "AIN1" at 1600.87,2328 h40
  text "GND" at 2764.03,2196.14 h72.83
  text "AIN2" at 1600.87,2184 h40
  text "GUI" at 2346.3,2153.74 h40
  text "MCU" at 2061.13,2147.64 h40
  text "BIN1" at 1600.87,2053.3 h40
  text "STALL" at 2045.08,2007.87 h40
  text "nFAULT" at 2283.46,1997.4 h40
  text "BIN2" at 1600.87,1926 h40
  text "STATUS LEDs" at 2070,1896 h40
  text "BOUT1" at 3324,1848 h40 r90
  text "nFAULT" at 1600.87,1788 h40
  text "VREF" at 1600.87,1650 h40
  text "BOUT2" at 3324,1626 h40 r90
  text "DRV8411A" at 2136.96,1594.49 h40
  text "TST" at 222,1581.91 h40 r90
  text "RST" at 322.91,1581.91 h40 r90
  text "TX" at 424.82,1581.91 h40 r90
  text "RX" at 524.44,1581.91 h40 r90
  text "3V3" at 624,1581.91 h40 r90
  text "GND" at 822.62,1581.91 h40 r90
  text "AIPROPI" at 1600.87,1518 h40
  text "BIPROPI" at 1600.87,1383.03 h40
  text "VCC" at 1600.87,1248 h40
  text "GND" at 1600.87,1110 h40
  text "AOUT2" at 3318,1002 h40 r90
  text "AOUT1" at 3318,786.5 h40 r90
  text "'.PRJ_Number'.PCB_Rev" at 2490,486 h108.27
  text "VM" at 1590,264 h40
  text "GND" at 2604,162 h40
  text "VM" at 1914,36 h40
  text "GND" at 2112,36 h40
  text ".Layer_Name" at 577,-858.49 h60
Bottom Overlay:
  text ".Layer_Name" at 577,-858.49 h60
Top Paste:
  text ".Layer_Name" at 577,-858.49 h60
Bottom Paste:
  text ".Layer_Name" at 577,-858.49 h60
Top Solder:
  text ".Layer_Name" at 577,-858.49 h60
  text ".Layer_Name" at 577,-858.49 h60
Bottom Solder:
  text ".Layer_Name" at 577,-858.49 h60
Drill Guide:
  text ".Layer_Name" at 577,-858.49 h60
M1 Board Outline:
  the board outline again, w10
  text ".Layer_Name" at 577,-858.49 h60
M2 Board Dimensions:
  rectangle: 0,-275 125,-150
  rectangle: 125,-400 500,-275
  lines w7: 0,-275 1000,-275 ; 125,-400 125,-150 ; 250,-400 250,-150 ; 500,-400 500,-150 ; 750,-400 750,-150 ; 0,-400 1000,-400 1000,-150 0,-150 0,-400
  text ".Layer_Name" at 577,-858.49 h60
M3 3D STEP Top:
  text ".Layer_Name" at 577,-858.49 h60
M4 3D STEP Bottom:
  text ".Layer_Name" at 577,-858.49 h60
M5 Assembly Top:
  lines w10: -292,-930.17 6308,-930.17 ; -292,-726.83 6310,-726.83 ; -292,-523.5 -292,-1133.5 3713,-1133.5 6310,-1133.5 6310,-523.5 -291.5,-523.5 -291.5,-1133.5 1284,-1133.5 ; 2173,-1133.5 2173,-523.5 ; 3440,-726.83 3440,-523.5 ; 4280,-726.83 4280,-523.5 ; 4902,-1140 4902,-937.17
  text "COMPONENTS MARKED 'DNP' SHOULD NOT BE POPULATED." at 1153.5,-318.5 h60
  text "ASSEMBLY VARIANT:" at 1153,-434 h60
  text ".VariantName" at 2189,-434 h60
  text "PCB VIEWED FROM TOP SIDE" at -228.5,-655.67 h60
  text "BOARD #:" at 2248,-655.67 h60
  text ".PRJ_Number" at 2793.5,-655.67 h60
  text "REV:" at 3638,-655.67 h60
  text ".PCB_Rev" at 3929.5,-655.67 h60
  text "SVN REV:" at 4476,-655.67 h60
  text ".VersionControl_RevNumber" at 4982,-655.67 h60
  text "TID #:" at 2248,-859 h60
  text ".TID" at 2793.5,-859 h60
  text "PLOT NAME =" at -228.5,-1064.34 h60
  text ".plot_File_Name" at 577,-1064.34 h60
  text "GENERATED    :" at 2250,-1064.34 h60
  text ".Print_Date" at 3119.5,-1064.34 h60
  text ".Print_Time" at 3848.5,-1064.34 h60
  text "TEXAS INSTRUMENTS" at 5113,-1064.34 h60
M6 Assembly Bottom:
  lines w10: -292.5,-727.33 6309.5,-727.33 ; -290.5,-930.67 6309.5,-930.67 ; 1115.5,-1140.5 1115.5,-937.67 ; 1737.5,-727.33 1737.5,-524 ; 2577.5,-727.33 2577.5,-524 ; 3844.5,-1134 3844.5,-524 ; 4733.5,-1134 6309,-1134 6309,-524 -292.5,-524 -292.5,-1134 2304.5,-1134 6309.5,-1134 6309.5,-524
  text "COMPONENTS MARKED 'DNP' SHOULD NOT BE POPULATED." at 6102,-318 h60
  text ".VariantName" at 5058,-434 h60
  text "ASSEMBLY VARIANT:" at 6097,-434 h60
  text ".VersionControl_RevNumber" at 1035.5,-656.17 h60
  text "SVN REV:" at 1541.5,-656.17 h60
  text ".PCB_Rev" at 2088,-656.17 h60
  text "REV:" at 2379.5,-656.17 h60
  text ".PRJ_Number" at 3224,-656.17 h60
  text "BOARD #:" at 3769.5,-656.17 h60
  text "PCB VIEWED FROM BOTTOM SIDE" at 6246,-656.17 h60
  text ".TID" at 3224,-859.5 h60
  text "TID #:" at 3769.5,-859.5 h60
  text "TEXAS INSTRUMENTS" at 904.5,-1064.84 h60
  text ".Print_Time" at 2169,-1064.84 h60
  text ".Print_Date" at 2898,-1064.84 h60
  text "GENERATED    :" at 3767.5,-1064.84 h60
  text ".plot_File_Name" at 5440.5,-1064.84 h60
  text "PLOT NAME =" at 6246,-1064.84 h60
M9 Title Sheet:
  drawing of 57 lines, arcs and shapes, not listed
  text "1" at 739.84,8036.5 h70
  text "2" at 3235.5,8036.5 h70
  text "3" at 5724.84,8036.5 h70
  text "4" at 8231.51,8036.5 h70
  text "5" at 10730.5,8036.5 h70
  text "6" at 13235.5,8036.5 h70
  text "A" at -416.5,6893.5 h70
  text "A" at 14383.5,6893.5 h70
  text "B" at -416.5,4513.5 h70
  text "B" at 14383.5,4513.5 h70
  text "C" at -416.5,2138.5 h70
  text "C" at 14383.5,2138.5 h70
  text "PROJECT TITLE:" at 11343.5,277.5 h45
  text ".PRJ_Title" at 11393.5,144.17 h70
  text "DESIGNED FOR:" at 11343.5,-23.5 h45
  text ".PRJ_Customer" at 11393.5,-163.5 h70
  text "D" at -416.5,-231.5 h70
  text "D" at 14383.5,-231.5 h70
  text "FILE NAME:" at 11343.5,-323.5 h45
  text ".PCB_File_Name_No_Path" at 11393.5,-443.5 h70
  text "Texas Instruments (TI) and/or its licensors do not warrant the accuracy or completeness of this specification" at 6374,-605.34 h45
  text "ENGINEER:" at 11343.5,-613.5 h45
  text "LAYOUT BY:" at 12848.5,-613.5 h45
  text "or any information contained therein. TI and/or its licensors do not warrant that this design will meet" at 6329.01,-718 h45
  text ".PRJ_Engineer" at 11393.5,-768.49 h70
  text ".PCB_Layout" at 12899,-768.49 h70
  text "the specifications, will be suitable for your application or fit for any particular purpose, or will operate in" at 6329.01,-830.67 h45
  text ".Layer_Name" at 577,-858.49 h60
  text "ALTIUM DESIGNER VERSION:" at 12848.5,-923.5 h45
  text "an implementation. TI and/or its licensors do not warrant that the design is production worthy. You should" at 6329.01,-943.33 h45
  text "completely validate and test your design implementation to confirm the system functionality for your application." at 6374,-1056 h45
  text ".print_Scale" at 11393.5,-1056.83 h70
  text ".Application_BuildNumber" at 12899,-1056.83 h70
  text "1" at 739.84,-1263.5 h70
  text "2" at 3235.5,-1263.5 h70
  text "3" at 5724.84,-1263.5 h70
  text "4" at 8231.51,-1263.5 h70
  text "5" at 10730.5,-1263.5 h70
  text "6" at 13235.5,-1263.5 h70
M10 Fab Notes:
  drawing of 189 lines, arcs and shapes, not listed
  text "DESIGN INFORMATION" at 12382.02,6356.17 h60
  text "MIN. TRACK WIDTH:" at 11737.46,6224.05 h60
  text "8" at 12833.7,6224.05 h60
  text "MIL" at 12988.46,6224.05 h60
  text "MIN. CLEARANCE:" at 11737.46,6099.92 h60
  text "0.2" at 12773.7,6099.93 h60
  text "mm" at 12988.46,6099.92 h60
  text "MIN. VIA PAD SIZE:" at 11737.46,5975.8 h60
  text "24" at 12803.71,5975.8 h60
  text "MIL" at 12988.46,5975.8 h60
  text "0.05mm (2MIL)" at 12432.46,5845.9 h60
  text "MINIMUM ANNULAR RING" at 11408.23,5837.67 h60
  text "EXTERNAL" at 13140.46,5837.67 h60
  text "PER" at 11608.23,5727.55 h60
  text "IPC-D-275 CLASS 2 LEVEL C" at 11828.23,5727.54 h60
  text "MIL, HOLES" at 13316.46,5627.07 h60
  text "+/-" at 12924,5618.48 h60
  text "+/-" at 13778,5618.48 h60
  text "REGISTRATION TOLERANCES:" at 11408.23,5617.42 h60
  text "METAL" at 12608,5617.42 h60
  text "5" at 13184.2,5617.42 h60
  text "3" at 14017.2,5617.42 h60
  text "MIL" at 14133.46,5617.42 h60
  text "HOLE SIZE TOLERANCE (UNLESS OTHERWISE SPECIFIED):" at 11408.23,5519.1 h60
  text "+/-" at 13778,5516.23 h60
  text "3" at 14017.2,5515.17 h60
  text "MIL" at 14133.46,5515.17 h60
  text "MATERIAL:" at 11333.46,5377.52 h60
  text "FR-4 High Tg" at 12319.9,5249 h60
  text "X" at 12175.46,5241.01 h60
  text "FR-408" at 11754.46,5236.49 h60
  text "OTHER" at 13242.46,5236.49 h60
  text "62 MIL (1.6mm) +/-10%" at 12074.56,5093.46 h60
  text "X" at 11954.46,5091.01 h60
  text "THICKNESS:" at 11408.23,5085.24 h60
  text "OTHER" at 13359.46,5085.24 h60
  text "TOLERANCE:" at 11408.23,4946.92 h60
  text "X" at 12256.46,4946.92 h60
  text "ANSI IPC-6012 TYPE 3 CLASS 2" at 12434.48,4946.92 h60
  text "OTHER +/-" at 12434.46,4802.73 h60
  text "BOW & TWIST:" at 11408.23,4657.54 h60
  text "X" at 12256.46,4657.54 h60
  text "ANSI IPC-6012 TYPE 3 CLASS 2" at 12434.48,4657.54 h60
  text "OTHER +/-" at 12434.46,4510.85 h60
  text "DRILLING:" at 11333.46,4380.23 h60
  text "NC_DRILL FILES" at 13094.46,4275.04 h60
  text "REFERENCE:" at 11408.23,4271.1 h60
  text "X" at 12065.46,4271.01 h60
  text "AS SHOWN" at 12243.46,4271.1 h60
  text "X" at 12966.46,4271.1 h60
  text "OTHER" at 13392.46,4128.85 h60
  text "PTH COPPER THICKNESS:" at 11407.91,4125.32 h60
  text "X" at 12547.14,4125.32 h60
  text "20-30 um" at 12675.14,4125.32 h60
  text "BOARD FINISH:" at 11333.46,3977.73 h60
  text "SILKSCREEN:" at 11488.68,3867.6 h60
  text "X" at 12446.46,3867.6 h60
  text "TOP" at 12563.46,3867.6 h60
  text "X" at 12956.46,3867.6 h60
  text "BOTTOM" at 13074.46,3867.6 h60
  text "SILKSCREEN COLOR:" at 11488.68,3712.41 h60
  text "X" at 12445.46,3712.41 h60
  text "WHITE" at 12563.46,3712.41 h60
  text "OTHER" at 13074.46,3712.41 h60
  text "X" at 12576.46,3568.96 h60
  text "GREEN" at 12694.46,3568.96 h60
  text "OTHER" at 13312.46,3568.96 h60
  text "SOLDER RESIST COLOR:" at 11488.68,3562.1 h60
  text "X" at 12576.46,3414.71 h60
  text "MATTE" at 12694.46,3414.71 h60
  text "SEMI-GLOSS" at 13312,3414.07 h60
  text "IMMERSION GOLD (ENIG)" at 12394.46,3241.94 h60
  text "ENEPIG" at 13732,3234.72 h60
  text "SURFACE FINISH:" at 11333.46,3233.72 h60
  text "X" at 12216.46,3233.72 h60
  text "IMM. TIN/SILVER OR EQUIV" at 11663,3096.4 h60
  text "OTHER" at 13094.46,3092.47 h60
  text "ARRAY/PANEL:" at 11333.46,2937.09 h60
  text "CUT AND TRIM PER M1 BOARD OUTLINE" at 12394.46,2928.87 h60
  text "N.C. ROUTE" at 12394.46,2792.9 h60
  text "X" at 13082.46,2792.9 h60
  text "V. SCORE" at 13260.46,2792.9 h60
  text "CERTIFICATION:" at 11333.46,2663.77 h60
  text "MATERIALS AND WORKMANSHIP FOR ALL PCBS" at 12058.46,2663.77 h60
  text "TO MEET OR EXCEED THE REQUIREMENTS OF:" at 12058.46,2569.71 h60
  text "X" at 11695.97,2441.08 h60
  text "ANSI IPC-A-600F CLASS ->" at 11823.96,2441.08 h60
  text "X" at 13471.97,2441.08 h60
  text "2" at 13581.96,2441.08 h60
  text "1" at 13266.96,2439.58 h60
  text "3" at 13935.96,2439.58 h60
  text "X" at 12507.97,2293.39 h60
  text "RoHS" at 12635.96,2293.39 h60
  text "OTHER" at 13280.36,2293.39 h60
  text "PER ORDER" at 13677.42,2293.39 h60
  text "ALL BOARDS MUST MEET OR EXCEED UL94-V0 REQUIREMENTS." at 11361,2139.57 h60
  text "PCB MUST BEAR THE UL94V-0 UL REGISTERED MATERIAL ID NUMBER" at 11361,2023.5 h60
  text "ADDITIONAL REQUIREMENTS:" at 11333.46,1854.08 h60
  text "MICROSECTION:" at 11408.23,1746.95 h60
  text "YES" at 12313.96,1746.95 h60
  text "REQUIRED" at 13175.46,1602.62 h60
  text "BARE BOARD ELEC. TEST:" at 11408.23,1599.76 h60
  text "NONE" at 12713.96,1599.76 h60
  text "X" at 13057.46,1599.76 h60
  text "PER ORDER" at 13767.46,1599.76 h60
  text "XX MIL VIAS REQUIRE NON-CONDUCTIVE FILL AND PLANARIZE" at 11576.38,1394.82 h59
  text "XX MIL VIAS REQUIRE CONDUCTIVE FILL AND PLANARIZE" at 11584.38,1290.84 h60
  text "OUTER XX MIL TRACES REQUIRE 50 OHM SINGLE-ENDED IMPEDANCE" at 11583.39,1127.46 h58
  text "LAYER 2 & 3 (INNER LAYERS) XX MIL WIDE, XX MIL SPACE / TRACES REQUIRE 100 OHM DIFFERENTIAL IMPEDANCE" at 11575.39,891.74 h60
  text ".Layer_Name" at 577,-858.49 h60
M11 Gerber Information:
  lines w10: -292,-930.17 6308,-930.17 ; -292,-726.83 6310,-726.83 ; -292,-523.5 -292,-1133.5 3713,-1133.5 6310,-1133.5 6310,-523.5 -291.5,-523.5 -291.5,-1133.5 1284,-1133.5 ; 2173,-1133.5 2173,-523.5 ; 3440,-726.83 3440,-523.5 ; 4280,-726.83 4280,-523.5 ; 4902,-1140 4902,-937.17
  text "ALL ARTWORK VIEWED FROM TOP SIDE" at -228.5,-655.67 h60
  text "BOARD #:" at 2248,-655.67 h60
  text ".PRJ_Number" at 2793.5,-655.67 h60
  text "REV:" at 3638,-655.67 h60
  text ".PCB_Rev" at 3929.5,-655.67 h60
  text "SVN REV:" at 4476,-655.67 h60
  text ".VersionControl_RevNumber" at 4982,-655.67 h60
  text "LAYER NAME =" at -228.5,-858.49 h60
  text "TID #:" at 2248,-859 h60
  text ".TID" at 2793.5,-859 h60
  text "PLOT NAME =" at -228.5,-1064.34 h60
  text ".plot_File_Name" at 577,-1064.34 h60
  text "GENERATED    :" at 2250,-1064.34 h60
  text ".Print_Date" at 3119.5,-1064.34 h60
  text ".Print_Time" at 3848.5,-1064.34 h60
  text "TEXAS INSTRUMENTS" at 5113,-1064.34 h60
M12 Stackup:
  drawing of 295 lines, arcs and shapes, not listed
  text "Layer" at 9821.59,7762.44 h60
  text "Name" at 10231.51,7762.44 h60
  text "Material" at 11171.25,7762.44 h60
  text "Thickness" at 12031.02,7762.44 h60
  text "Constant" at 12680.85,7762.44 h60
  text "Board Layer Stack" at 13250.71,7762.44 h60
  text "Top Overlay" at 10231.51,7642.44 h60
  text "Top Solder" at 10231.51,7522.44 h60
  text "Solder Resist" at 11171.25,7522.44 h60
  text "0.40mil" at 12031.02,7522.44 h60
  text "3.5" at 12680.85,7522.44 h60
  text "1" at 9821.59,7402.44 h60
  text "Top Layer" at 10231.51,7402.44 h60
  text "2.80mil" at 12031.02,7402.44 h60
  text "Dielectric 1" at 10231.51,7282.44 h60
  text "FR-4" at 11171.25,7282.44 h60
  text "8.00mil" at 12031.02,7282.44 h60
  text "4.2" at 12680.85,7282.44 h60
  text "2" at 9821.59,7162.44 h60
  text "Signal Layer 1" at 10231.51,7162.44 h60
  text "1.40mil" at 12031.02,7162.44 h60
  text "Dielectric 2" at 10231.51,7042.44 h60
  text "FR-4" at 11171.25,7042.44 h60
  text "37.20mil" at 12031.02,7042.44 h60
  text "4.2" at 12680.85,7042.44 h60
  text "3" at 9821.59,6922.44 h60
  text "Signal Layer 2" at 10231.51,6922.44 h60
  text "1.40mil" at 12031.02,6922.44 h60
  text "Dielectric 3" at 10231.51,6802.44 h60
  text "FR-4" at 11171.25,6802.44 h60
  text "8.00mil" at 12031.02,6802.44 h60
  text "4.2" at 12680.85,6802.44 h60
  text "4" at 9821.59,6682.44 h60
  text "Bottom Layer" at 10231.51,6682.44 h60
  text "2.80mil" at 12031.02,6682.44 h60
  text "Bottom Solder" at 10231.51,6562.44 h60
  text "Solder Resist" at 11171.25,6562.44 h60
  text "0.40mil" at 12031.02,6562.44 h60
  text "3.5" at 12680.85,6562.44 h60
  text "Bottom Overlay" at 10231.51,6442.44 h60
  text ".Layer_Name" at 577,-858.49 h60
M13 Component Bodies Top:
  text ".Layer_Name" at 577,-858.49 h60
M14 Component Bodies Bottom:
  text ".Layer_Name" at 577,-858.49 h60
M15 Courtyards Top:
  text ".Layer_Name" at 577,-858.49 h60
M16 Courtyards Bottom:
  text ".Layer_Name" at 577,-858.49 h60
Drill Drawing:
  circle w10: c5363.72,3325.6 r16.58
  circle w10: c5363.72,3325.6 r27.63
  circle w10: c5363.72,3076.96 r27.63
  lines w10: 5336.09,2455.36 5363.72,2427.74 5391.34,2455.36 5363.72,2482.99 5336.09,2455.36 ; 5336.09,2552.06 5391.34,2552.06 5391.34,2607.31 5336.09,2607.31 5336.09,2552.06 ; 5336.09,2731.63 5391.34,2731.63 5363.72,2676.38 5336.09,2731.63 ; 5336.09,2800.7 5336.09,2814.51 5349.9,2828.32 5336.09,2842.14 5336.09,2855.95 5349.9,2855.95 5363.72,2842.14 5377.53,2855.95 5391.34,2855.95 5391.34,2842.14 5377.53,2828.32 5391.34,2814.51 5391.34,2800.7 5377.53,2800.7 5363.72,2814.51 5349.9,2800.7 5336.09,2800.7 ; 5336.09,2938.83 5349.9,2938.83 5363.72,2925.02 5377.53,2938.83 5391.34,2938.83 5377.53,2952.64 5391.34,2966.46 5377.53,2966.46 5363.72,2980.27 5349.9,2966.46 5336.09,2966.46 5349.9,2952.64 5336.09,2938.83 ; 5336.09,3187.47 5349.9,3187.47 5349.9,3173.66 5377.53,3173.66 5377.53,3187.47 5391.34,3187.47 5391.34,3215.1 5377.53,3215.1 5377.53,3228.91 5349.9,3228.91 5349.9,3215.1 5336.09,3215.1 5336.09,3187.47
  lines w12: 5286,2390.44 8517.49,2390.44 ; 5286,3385 8517.49,3385 ; 5623.86,2266.12 5623.86,3509.32 ; 5955.86,2266.12 5955.86,3509.32 ; 6592.43,2266.12 6592.43,3509.32 ; 6851.57,2266.12 6851.57,3509.32 ; 7226.72,2266.12 7226.72,3509.32 ; 7951.05,2266.12 7951.05,3509.32 ; 5286,2266.12 8517.49,2266.12 8517.49,3509.32 5286,3509.32 5286,2266.12
  text "Symbol" at 5360.59,3422.3 h72
  text "Quantity" at 5661.16,3422.3 h72
  text "Finished Hole Size" at 5993.16,3422.3 h72
  text "Plated" at 6629.72,3422.3 h72
  text "Hole Type" at 6888.86,3422.3 h72
  text "Drill Layer Pair" at 7264.02,3422.3 h72
  text "Hole Tolerance" at 7988.35,3422.3 h72
  text "221" at 5661.16,3297.98 h60
  text "12.00mil (0.305mm)" at 5993.16,3297.98 h60
  text "PTH" at 6629.72,3297.98 h60
  text "Round" at 6888.86,3297.98 h60
  text "Top Layer - Bottom Layer" at 7264.02,3297.98 h60
  text "10" at 5661.16,3173.66 h60
  text "17.72mil (0.450mm)" at 5993.16,3173.66 h60
  text "PTH" at 6629.72,3173.66 h60
  text "Round" at 6888.86,3173.66 h60
  text "Top Layer - Bottom Layer" at 7264.02,3173.66 h60
  text "3" at 5661.16,3049.34 h60
  text "33.47mil (0.850mm)" at 5993.16,3049.34 h60
  text "PTH" at 6629.72,3049.34 h60
  text "Round" at 6888.86,3049.34 h60
  text "Top Layer - Bottom Layer" at 7264.02,3049.34 h60
  text "30" at 5661.16,2925.02 h60
  text "40.00mil (1.016mm)" at 5993.16,2925.02 h60
  text "PTH" at 6629.72,2925.02 h60
  text "Round" at 6888.86,2925.02 h60
  text "Top Layer - Bottom Layer" at 7264.02,2925.02 h60
  text "28" at 5661.16,2800.7 h60
  text "43.31mil (1.100mm)" at 5993.16,2800.7 h60
  text "PTH" at 6629.72,2800.7 h60
  text "Round" at 6888.86,2800.7 h60
  text "Top Layer - Bottom Layer" at 7264.02,2800.7 h60
  text "+/-1.97mil" at 7988.35,2800.7 h60
  text "5" at 5661.16,2676.38 h60
  text "45.28mil (1.150mm)" at 5993.16,2676.38 h60
  text "PTH" at 6629.72,2676.38 h60
  text "Round" at 6888.86,2676.38 h60
  text "Top Layer - Bottom Layer" at 7264.02,2676.38 h60
  text "10" at 5661.16,2552.06 h60
  text "51.18mil (1.300mm)" at 5993.16,2552.06 h60
  text "PTH" at 6629.72,2552.06 h60
  text "Round" at 6888.86,2552.06 h60
  text "Top Layer - Bottom Layer" at 7264.02,2552.06 h60
  text "2" at 5661.16,2427.74 h60
  text "23.62mil (0.600mm)" at 5993.16,2427.74 h60
  text "PTH" at 6629.72,2427.74 h60
  text "Slot" at 6888.86,2427.74 h60
  text "Top Layer - Bottom Layer" at 7264.02,2427.74 h60
  text "309 Total" at 5661.16,2303.42 h60
  text "Slot definitions :" at 5360.59,2216.39 h60
  text "Routed Path Length" at 5811.31,2216.39 h60
  text "= Calculated from tool start centre position to tool end centre position." at 6351.05,2216.39 h60
  text "Hole Length" at 5811.31,2166.67 h60
  text "= Routed Path Length + Tool Size = Slot length as defined in the PCB layout" at 6151.24,2166.67 h60
  text ".Layer_Name" at 577,-858.49 h60
Mechanical 17:
  text ".Layer_Name" at 577,-858.49 h60
Mechanical 18:
  text ".Layer_Name" at 577,-858.49 h60
Mechanical 19:
  text ".Layer_Name" at 577,-858.49 h60

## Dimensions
0,-400 to 1000,-400 on M2 Board Dimensions
0,0 to 0,2682 on M2 Board Dimensions
0,0 to 3360,0 on M2 Board Dimensions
